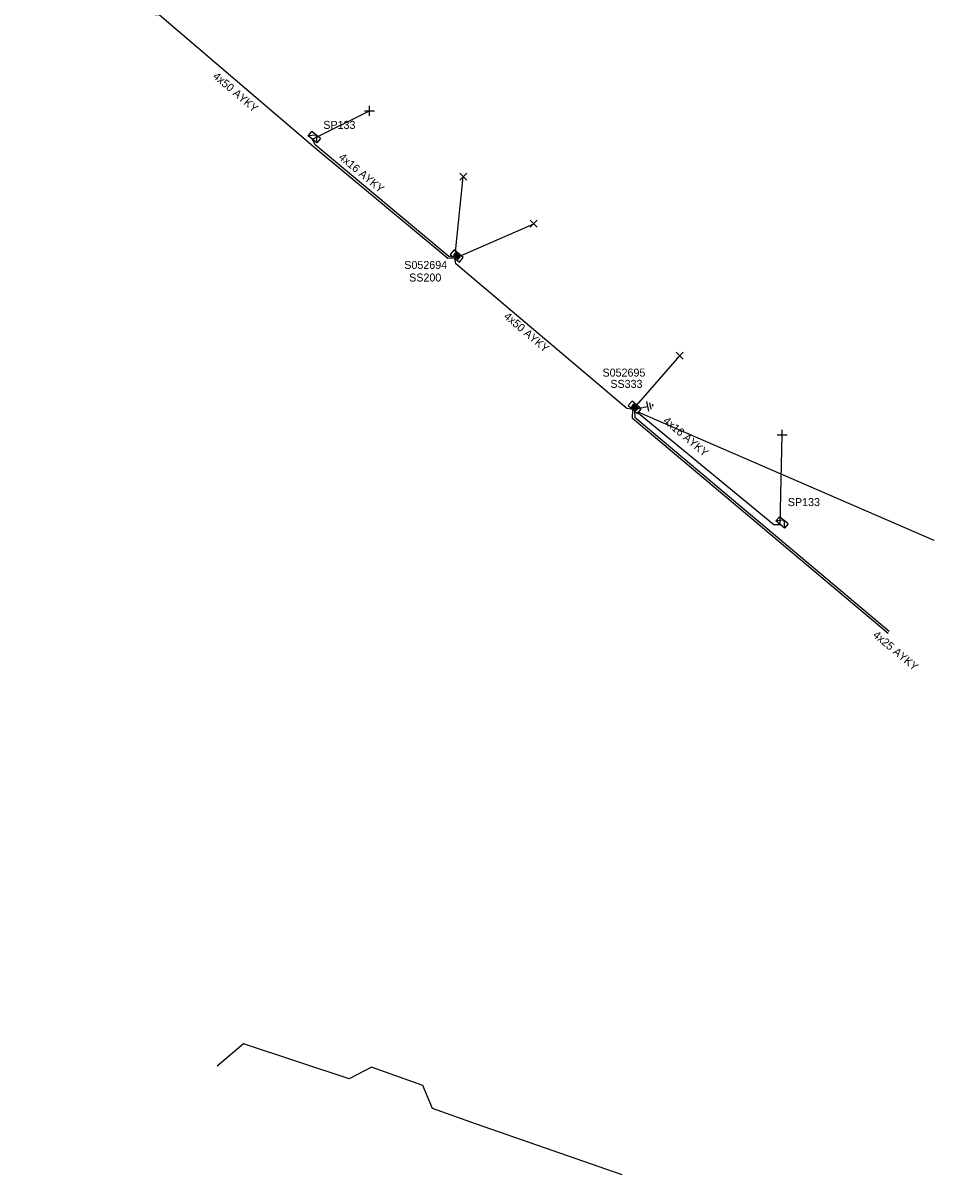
# Model space of a CAD drawing. Extents: x -717562 to -713845, y -1151196 to -1143903.
# Drawn here: x -715257.8 to -715143.9, y -1151195.6 to -1151051.7 of the extents above; entities that cross this region are included whole.
import ezdxf

# ---------------------------------------------------------------- set-up
doc = ezdxf.new("R2010")
doc.units = 0
for name, color, linetype in [('Vrstva 1', 7, 'Continuous'), ('Vrstva 14', 7, 'Continuous'), ('Vrstva 15', 7, 'Continuous'), ('Vrstva 28', 7, 'Continuous'), ('Vrstva 29', 7, 'Continuous'), ('Vrstva 30', 7, 'Continuous'), ('Vrstva 31', 7, 'Continuous'), ('Vrstva 33', 7, 'Continuous'), ('Vrstva 34', 7, 'Continuous'), ('Vrstva 5', 7, 'Continuous'), ('Vrstva 52', 7, 'Continuous'), ('Vrstva 54', 7, 'Continuous'), ('Vrstva 59', 7, 'Continuous'), ('Vrstva 6', 7, 'Continuous'), ('Vrstva 8', 7, 'Continuous'), ('Vrstva 9', 7, 'Continuous')]:
    doc.layers.add(name, color=color, linetype=linetype)

# ---------------------------------------------------------------- blocks, each defined once
blk = doc.blocks.new('NN800')
at = {"layer": 'Vrstva 1'}
for points in [[(-0.44, 0.44), (0.44, -0.44)], [(-0.44, -0.44), (0.44, 0.44)]]:
    blk.add_lwpolyline(points, dxfattribs=at)
blk = doc.blocks.new('NN620')
at = {"layer": 'Vrstva 8'}
for points in [[(0.75, 0), (-0.75, 0)], [(-0.75, 0), (-0.75, -0.75)], [(0.75, -0.75), (0.75, 0)], [(-0.75, -0.75), (0.75, -0.75)], [(0.37, -0.18), (-0.38, -0.18)], [(-0.38, -0.18), (-0.38, -0.56)], [(-0.38, -0.56), (0.37, -0.56)], [(0.32, -0.23), (-0.33, -0.23)], [(-0.33, -0.23), (-0.33, -0.51)], [(-0.33, -0.51), (0.32, -0.51)], [(0.27, -0.27), (-0.28, -0.27)], [(-0.28, -0.27), (-0.28, -0.46)], [(-0.28, -0.46), (0.27, -0.46)], [(0.23, -0.32), (-0.23, -0.32)], [(-0.23, -0.32), (-0.23, -0.42)], [(-0.23, -0.42), (0.23, -0.42)], [(-0.19, -0.37), (0.19, -0.37)], [(0.23, -0.42), (0.23, -0.32)], [(0.27, -0.46), (0.27, -0.27)], [(0.32, -0.51), (0.32, -0.23)], [(0.37, -0.56), (0.37, -0.18)]]:
    blk.add_lwpolyline(points, dxfattribs=at)
blk = doc.blocks.new('NN630')
at = {"layer": 'Vrstva 9'}
for points in [[(0, -0.7), (-0.7, 0)], [(-0.7, -0.7), (-0.7, 0), (0.7, 0), (0.7, -0.7)], [(-0.7, -0.7), (0.7, -0.7)], [(0, -0.7), (0.7, 0)]]:
    blk.add_lwpolyline(points, dxfattribs=at)
blk = doc.blocks.new('NN810')
at = {"layer": 'Vrstva 14'}
for points in [[(0, -0.64), (0, -1.89)], [(0.63, -1.89), (-0.62, -1.89)], [(0.39, -2.2), (-0.4, -2.2)], [(0, -2.52), (-0.12, -2.52)], [(0.14, -2.52), (0, -2.52)]]:
    blk.add_lwpolyline(points, dxfattribs=at)

msp = doc.modelspace()

# ---------------------------------------------------------------- linework, layer by layer
at = {"layer": 'Vrstva 5'}
for points in [[(-715203.93, -1151080.94), (-715204.06, -1151081.07), (-715204.68, -1151081.09), (-715221.51, -1151067.08), (-715240.68, -1151050.7), (-715258.96, -1151049.4), (-715259.97, -1151047.29), (-715260.01, -1151044.32)], [(-715181.68, -1151099.82), (-715181.78, -1151099.92), (-715182.31, -1151099.83), (-715203.65, -1151081.74), (-715203.79, -1151081.06)], [(-715149.65, -1151127.94), (-715181.58, -1151101.09), (-715181.55, -1151099.96)], [(-715182.9, -1151195.6), (-715201.23, -1151189.22), (-715206.57, -1151187.29), (-715207.78, -1151184.43), (-715214.21, -1151182.15), (-715217, -1151183.58), (-715230.19, -1151179.22), (-715233.48, -1151182)]]:
    msp.add_lwpolyline(points, dxfattribs=at)
at = {"layer": 'Vrstva 52'}
for points in [[(-715204.11, -1151080.77), (-715204.25, -1151080.91), (-715204.53, -1151080.83), (-715221.26, -1151066.9), (-715221.57, -1151066.2)], [(-715181.35, -1151100.09), (-715181.31, -1151100.93), (-715149.52, -1151127.67)], [(-715181, -1151100.33), (-715180.64, -1151100.57), (-715163.95, -1151114.31), (-715163.13, -1151114.33)]]:
    msp.add_lwpolyline(points, dxfattribs=at)
at = {"layer": 'Vrstva 59'}
for points in [[(-715221.57, -1151066.2), (-715214.44, -1151062.63)], [(-715203.71, -1151080.24), (-715202.75, -1151070.88)], [(-715203.09, -1151080.75), (-715193.94, -1151076.75)], [(-715181.11, -1151099.46), (-715175.69, -1151093.25)], [(-715180.92, -1151100.24), (-715143.92, -1151116.28)], [(-715163.13, -1151114.34), (-715162.88, -1151103.13)]]:
    msp.add_lwpolyline(points, dxfattribs=at)

# ---------------------------------------------------------------- block references
at = {"layer": 'Vrstva 15', "rotation": 101.7663528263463}
msp.add_blockref('NN810', (-715181.55, -1151099.96), dxfattribs=at)
at = {"layer": 'Vrstva 28'}
for p, rotation in [((-715203.79, -1151081.06), 140.08745265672), ((-715181.55, -1151099.96), 139.68310283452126)]:
    msp.add_blockref('NN620', p, dxfattribs=dict(at, rotation=rotation))
at = {"layer": 'Vrstva 31'}
for p, rotation in [((-715221.57, -1151066.2), 139.9887137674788), ((-715163.13, -1151114.34), 140.1574944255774)]:
    msp.add_blockref('NN630', p, dxfattribs=dict(at, rotation=rotation))
at = {"layer": 'Vrstva 34'}
for p, rotation in [((-715214.44, -1151062.63), 44.99999995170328), ((-715162.88, -1151103.13), 45)]:
    msp.add_blockref('NN800', p, dxfattribs=dict(at, rotation=rotation))
for p in [(-715202.75, -1151070.88), (-715193.94, -1151076.75), (-715175.69, -1151093.25)]:
    msp.add_blockref('NN800', p, dxfattribs=at)

# ---------------------------------------------------------------- texts
at = {"layer": 'Vrstva 29'}
for s, p in [('S052694', (-715210.11, -1151082.4)), ('S052695', (-715185.34, -1151095.85))]:
    msp.add_text(s, height=1, dxfattribs=at).set_placement(p)
at = {"layer": 'Vrstva 30'}
for s, p in [('SS200', (-715209.5, -1151083.97)), ('SS333', (-715184.36, -1151097.26))]:
    msp.add_text(s, height=1, dxfattribs=at).set_placement(p)
at = {"layer": 'Vrstva 33'}
for p in [(-715220.23, -1151064.9), (-715162.18, -1151112.03)]:
    msp.add_text('SP133', height=1, dxfattribs=at).set_placement(p)
at = {"layer": 'Vrstva 54'}
for rotation, p in [(320.219, (-715218.4, -1151068.58)), (319.709, (-715177.85, -1151101.51))]:
    msp.add_text('4x16 AYKY', height=1, rotation=rotation, dxfattribs=at).set_placement(p)
at = {"layer": 'Vrstva 6'}
for s, rotation, p in [('4x50 AYKY', 319.495, (-715234.11, -1151058.46)), ('4x50 AYKY', 319.711, (-715197.76, -1151088.47)), ('4x25 AYKY', 319.937, (-715151.64, -1151128.27))]:
    msp.add_text(s, height=1, rotation=rotation, dxfattribs=at).set_placement(p)

doc.saveas('drawing.dxf')
